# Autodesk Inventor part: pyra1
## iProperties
Created: 2004-12
Part Number: pyra1
Cost Center: 0.001 kg
Document SubType Name: Modeling
Designer: jwagner
Authority: 1204 mm^3
Manufacturer: Standard
Standards Organization: Custom
Author: jwagner
SaveDate: 2004-11-30
SaveTime: 11:54
TotalMass: 0.001 kg
TotalVolume: 1204 mm^3
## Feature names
1. Extrusion1
